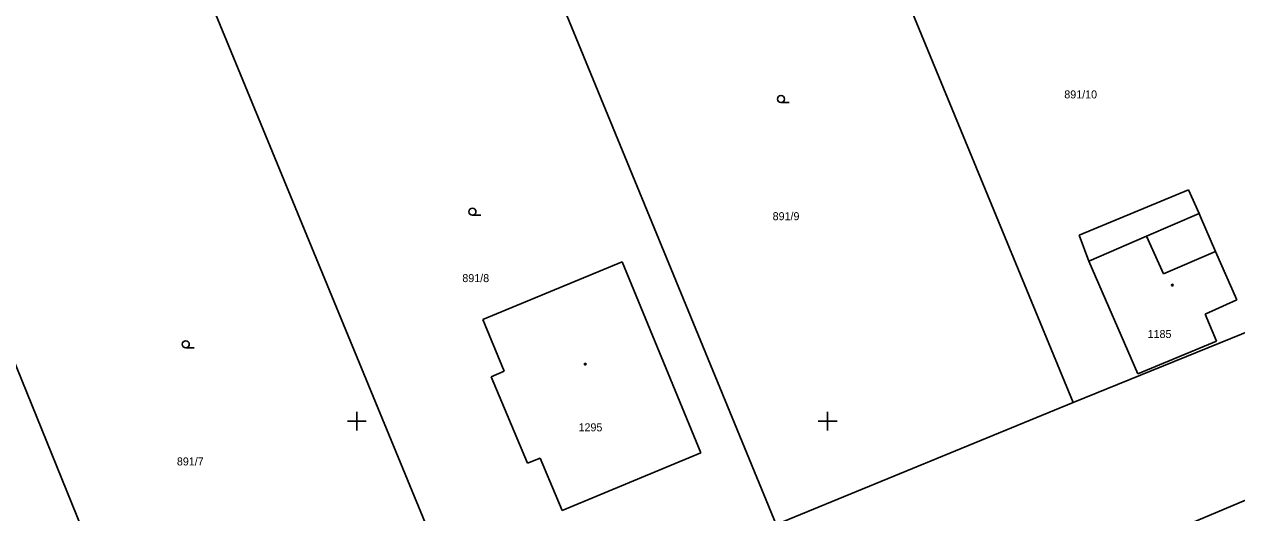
# Model space of a CAD drawing. Extents: x -711081 to -709338, y -1025122 to -1024092.
# Drawn here: x -710242.7 to -710178.3, y -1024754.9 to -1024728.9 of the extents above; entities that cross this region are included whole.
import ezdxf

# ---------------------------------------------------------------- set-up
doc = ezdxf.new("R2010")
doc.units = 0
for name, color, linetype in [('Z_hektometricka_sit', 7, 'Continuous'), ('Z_katastr_cisla_pozemkova', 7, 'Continuous'), ('Z_katastr_cisla_stavebni', 7, 'Continuous'), ('Z_katastr_hranice', 7, 'Continuous'), ('Z_katastr_vnitrni_kresba', 7, 'Continuous'), ('Z_katastr_znacky_budov', 7, 'Continuous'), ('Z_katastr_znacky_kultur', 7, 'Continuous')]:
    doc.layers.add(name, color=color, linetype=linetype)

msp = doc.modelspace()

# ---------------------------------------------------------------- linework, layer by layer
at = {"layer": 'Z_hektometricka_sit'}
for p, q in [((-710225.5, -1024750), (-710224.5, -1024750)), ((-710225, -1024749.5), (-710225, -1024750.5)), ((-710200.5, -1024750), (-710199.5, -1024750)), ((-710200, -1024749.5), (-710200, -1024750.5))]:
    msp.add_line(p, q, dxfattribs=at)
at = {"layer": 'Z_katastr_hranice'}
for p, q in [((-710186.96, -1024749), (-710202.27, -1024711.87)), ((-710202.73, -1024755.48), (-710217.97, -1024718.42)), ((-710218.68, -1024761.93), (-710233.84, -1024725.07)), ((-710234.43, -1024768.38), (-710249.43, -1024731.47)), ((-710186.65, -1024740.11), (-710180.84, -1024737.7)), ((-710180.84, -1024737.7), (-710180.28, -1024738.97)), ((-710180.28, -1024738.97), (-710180.2, -1024739.15)), ((-710180.2, -1024739.15), (-710179.4, -1024740.98)), ((-710186.13, -1024741.49), (-710186.65, -1024740.11)), ((-710179.4, -1024740.98), (-710178.28, -1024743.56)), ((-710218.3, -1024744.59), (-710210.91, -1024741.53)), ((-710210.91, -1024741.53), (-710206.73, -1024751.68)), ((-710183.53, -1024747.49), (-710186.13, -1024741.49)), ((-710186.96, -1024749), (-710171.13, -1024742.56)), ((-710178.28, -1024743.56), (-710179.96, -1024744.32)), ((-710217.17, -1024747.34), (-710218.3, -1024744.59)), ((-710179.96, -1024744.32), (-710179.36, -1024745.75)), ((-710179.36, -1024745.75), (-710183.53, -1024747.49)), ((-710217.86, -1024747.64), (-710217.17, -1024747.34)), ((-710215.94, -1024752.23), (-710217.86, -1024747.64)), ((-710202.73, -1024755.48), (-710186.96, -1024749)), ((-710215.26, -1024751.97), (-710215.94, -1024752.23)), ((-710214.09, -1024754.75), (-710215.26, -1024751.97)), ((-710206.73, -1024751.68), (-710214.09, -1024754.75)), ((-710174.12, -1024752.64), (-710190.92, -1024759.7))]:
    msp.add_line(p, q, dxfattribs=at)
at = {"layer": 'Z_katastr_vnitrni_kresba'}
for p, q in [((-710183.07, -1024740.17), (-710180.28, -1024738.97)), ((-710186.13, -1024741.49), (-710183.07, -1024740.17)), ((-710183.07, -1024740.17), (-710182.16, -1024742.17)), ((-710182.16, -1024742.17), (-710179.4, -1024740.98))]:
    msp.add_line(p, q, dxfattribs=at)
at = {"layer": 'Z_katastr_znacky_budov'}
for centre in [(-710181.702, -1024742.77), (-710212.872, -1024746.97)]:
    msp.add_circle(centre, 0.0437, dxfattribs=at)
at = {"layer": 'Z_katastr_znacky_kultur'}
for p, q in [((-710202.478, -1024733.07), (-710202.041, -1024733.07)), ((-710218.858, -1024739.06), (-710218.421, -1024739.06)), ((-710234.078, -1024746.1), (-710233.641, -1024746.1))]:
    msp.add_line(p, q, dxfattribs=at)
for centre in [(-710202.478, -1024732.882), (-710218.858, -1024738.872), (-710234.078, -1024745.912)]:
    msp.add_circle(centre, 0.187, dxfattribs=at)

# ---------------------------------------------------------------- texts
at = {"layer": 'Z_katastr_cisla_pozemkova'}
for s, p in [('891/10', (-710187.435, -1024732.85)), ('891/9', (-710202.919, -1024739.32)), ('891/8', (-710219.394, -1024742.61)), ('891/7', (-710234.549, -1024752.35))]:
    msp.add_text(s, height=0.425, dxfattribs=at).set_placement(p)
at = {"layer": 'Z_katastr_cisla_stavebni'}
for s, p in [('1185', (-710183.011, -1024745.58)), ('1295', (-710213.225, -1024750.539))]:
    msp.add_text(s, height=0.425, dxfattribs=at).set_placement(p)

doc.saveas('drawing.dxf')
